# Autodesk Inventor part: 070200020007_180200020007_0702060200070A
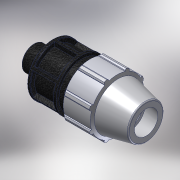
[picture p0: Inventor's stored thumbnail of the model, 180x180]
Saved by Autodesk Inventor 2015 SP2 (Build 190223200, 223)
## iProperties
Created: 2017-02
Part Number: 070200020007_180200020007_0702060200070A
Material: PVC-Piping
Description: PLASSON MALE ADAPTOR 20-3/4"
Document SubType Name: Modeling
Designer: KIM
Mass: 92.6774 g
Surface Area: 199.44 cm^2
Volume: 66.1981 cm^3
Density: 1.4 g/cm^3
Appearance: PTFE
Author: KIM
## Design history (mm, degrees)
derived "07020.ipt"
feature "Solid1::07020.ipt"
tag "TaggingFeature1"
body "Solid1"
other parameters: "d4" = 13.14286, "d5" = 23, "d7" = 48, "d8" = 36, "d9" = 13.14286, "d11" = 2.62857, "d12" = 38.4, "d13" = 120 deg, "d15" = 12 deg, "d16" = 43.2, "d18" = 1, "d19" = 35 deg, "d20" = 17.5 deg, "d21" = 44.64, "d23" = 0, "d25" = 360 deg, "d27" = 0.96, "d34" = 2.4, "d36" = 0, "d42" = 23, "d43" = 1.44, "d46" = 0.6, "d49" = 71, "d51" = 92, "d52" = 18, "d53" = 0.4, "d55" = 360 deg, "d57" = 26.441, "d58" = 18.5087, "d59" = 18.4, "E_" = 48, "H_" = 92, "l_" = 71, "l_2" = 18, "R_" = 26.441
